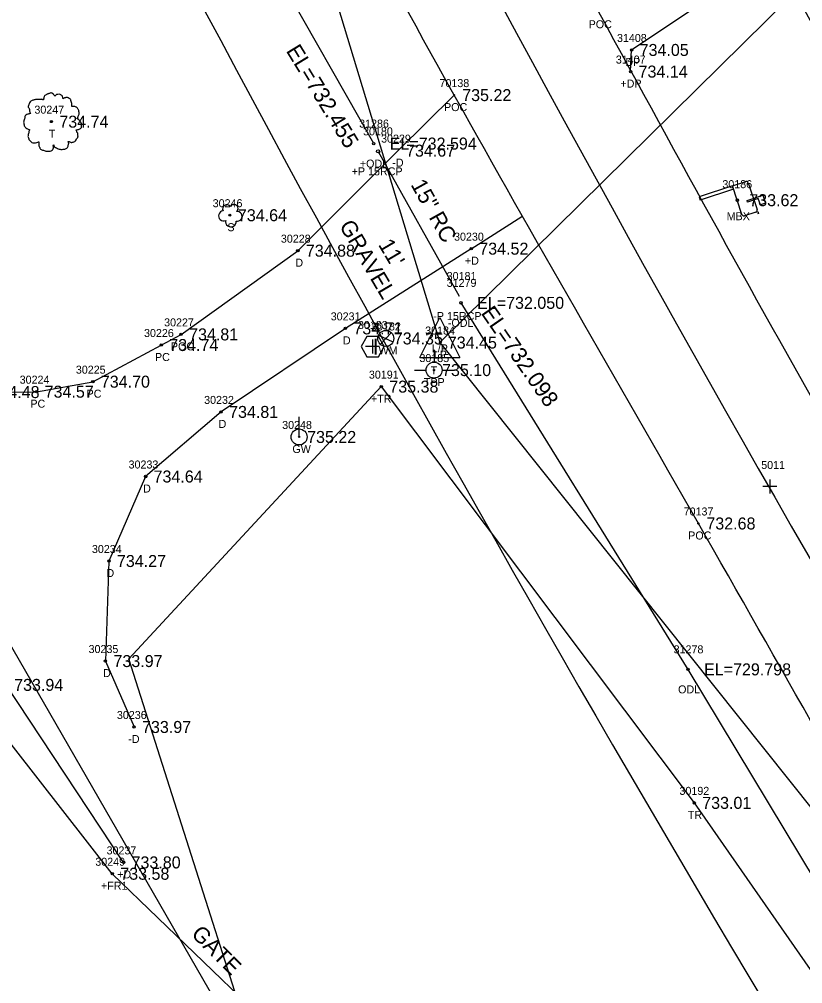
# Model space of a CAD drawing. Extents: x 1375131 to 1378678, y 999028 to 1004053.
# Drawn here: x 1376880.1 to 1376977.9, y 1002249 to 1002369.5 of the extents above; entities that cross this region are included whole.
import ezdxf

# ---------------------------------------------------------------- set-up
doc = ezdxf.new("R2010")
doc.units = 0
for name, color, linetype in [('Default', 7, 'Continuous'), ('RD_EX_BldgApp', 7, 'Continuous'), ('RD_EX_BldgApp_txCode', 7, 'Continuous'), ('RD_EX_DR_Pipe', 7, 'Continuous'), ('RD_EX_DR_Pipe_txCode', 7, 'Continuous'), ('RD_EX_Driveway', 7, 'Continuous'), ('RD_EX_Driveway_txCode', 7, 'Continuous'), ('RD_EX_DV_Prop', 7, 'Continuous'), ('RD_EX_Fence_Other', 7, 'Continuous'), ('RD_EX_Fence_Other_txCode', 7, 'Continuous'), ('RD_EX_H2O', 7, 'Continuous'), ('RD_EX_H2O_txCode', 7, 'Continuous'), ('RD_EX_Road', 7, 'Continuous'), ('RD_EX_Road_txCode', 7, 'Continuous'), ('RD_EX_RW', 7, 'Continuous'), ('RD_EX_SU_Elec', 7, 'Continuous'), ('RD_EX_SU_TX_Nonpot', 7, 'Continuous'), ('RD_EX_TX_BldgApp_ELEV', 7, 'Continuous'), ('RD_EX_TX_Driveway_ELEV', 7, 'Continuous'), ('RD_EX_TX_Fence_Other_ELEV', 7, 'Continuous'), ('RD_EX_TX_H2O_ELEV', 7, 'Continuous'), ('RD_EX_TX_Road_ELEV', 7, 'Continuous'), ('RD_EX_TX_UT_ELEV', 7, 'Continuous'), ('RD_EX_TX_VEG_ELEV', 7, 'Continuous'), ('RD_EX_UT', 7, 'Continuous'), ('RD_EX_UT_txCode', 7, 'Continuous'), ('RD_EX_VEG', 7, 'Continuous'), ('RD_EX_VEG_txCode', 7, 'Continuous'), ('RD_HC_Cl', 7, 'Continuous'), ('RD_SMD_Locator', 7, 'Continuous'), ('RD_TX_Drainage', 7, 'Continuous'), ('RD_TX_Misc2', 7, 'Continuous'), ('RD_TX_Pipe_ElevEX', 7, 'Continuous')]:
    doc.layers.add(name, color=color, linetype=linetype)

msp = doc.modelspace()

# ---------------------------------------------------------------- linework, layer by layer
at = {"layer": 'Default'}
for p, q in [((1376924.21, 1002329.43), (1376924.21, 1002327.68)), ((1376925.08, 1002328.56), (1376923.33, 1002328.56)), ((1376973.86, 1002311.95), (1376973.86, 1002310.2)), ((1376974.73, 1002311.07), (1376972.98, 1002311.07))]:
    msp.add_line(p, q, dxfattribs=at)
at = {"layer": 'RD_EX_BldgApp'}
for p, q in [((1376969.17, 1002348.65), (1376970.83, 1002349.2)), ((1376969.17, 1002348.65), (1376964.99, 1002347.27)), ((1376969.31, 1002348.25), (1376965.12, 1002346.87)), ((1376970.36, 1002345.06), (1376969.17, 1002348.65)), ((1376971.15, 1002349.04), (1376972.26, 1002345.69)), ((1376964.99, 1002347.27), (1376965.12, 1002346.87)), ((1376970.99, 1002346.81), (1376972.98, 1002347.47)), ((1376971.05, 1002346.63), (1376970.99, 1002346.81)), ((1376972.4, 1002347.07), (1376971.05, 1002346.63)), ((1376972.66, 1002346.28), (1376972.4, 1002347.07)), ((1376972.98, 1002347.47), (1376973.3, 1002346.49)), ((1376973.3, 1002346.49), (1376972.66, 1002346.28)), ((1376972.1, 1002345.37), (1376970.68, 1002344.9)), ((1376972.1, 1002345.37), (1376972.34, 1002345.45)), ((1376972.42, 1002345.21), (1376972.3, 1002345.17)), ((1376972.34, 1002345.45), (1376972.42, 1002345.21))]:
    msp.add_line(p, q, dxfattribs=at)
for centre, start, end in [((1376970.91, 1002348.96), 18.3234, 108.3234), ((1376972.02, 1002345.61), 288.3234, 18.3234), ((1376970.6, 1002345.14), 198.3234, 288.3234)]:
    msp.add_arc(centre, 0.25, start, end, dxfattribs=at)
at = {"layer": 'RD_EX_DR_Pipe'}
msp.add_line((1376924.89, 1002352.96), (1376935.01, 1002334.88), dxfattribs=at)
at = {"layer": 'RD_EX_Driveway'}
msp.add_line((1376936.53, 1002340.8), (1376942.86, 1002344.81), dxfattribs=at)
for points in [[(1376911, 1002403.28), (1376904.12, 1002405.28), (1376902.61, 1002405.41), (1376898.14, 1002404.97), (1376891.9, 1002404.07), (1376878.32, 1002397.35), (1376865.82, 1002389.76), (1376856.77, 1002381.29), (1376852.77, 1002374.27), (1376851.72, 1002365.55), (1376852.45, 1002354.79), (1376854.03, 1002345.76), (1376868.77, 1002323.94), (1376875.45, 1002322.88), (1376882.22, 1002322.93), (1376889.24, 1002324.18), (1376897.79, 1002328.76), (1376900.27, 1002330.09), (1376914.86, 1002340.55), (1376927.38, 1002353.05), (1376934.4, 1002359.99)], [(1376956.44, 1002362.93), (1376956.57, 1002365.63), (1376967.2, 1002372.83), (1376960.83, 1002383.95), (1376951.12, 1002382.71), (1376946.21, 1002383.24)], [(1376893.08, 1002264.11), (1376878.41, 1002286.29), (1376842.77, 1002332.19), (1376829.79, 1002366.92)], [(1376936.53, 1002340.8), (1376920.8, 1002330.84), (1376905.27, 1002320.4), (1376895.83, 1002312.33), (1376891.25, 1002301.77), (1376890.82, 1002289.27), (1376894.39, 1002281.03)]]:
    msp.add_lwpolyline(points, dxfattribs=at)
at = {"layer": 'RD_EX_DV_Prop'}
msp.add_lwpolyline([(1376724.42, 1002117.06), (1376637.57, 1002230.63), (1376389.38, 1002558.79), (1376664.3, 1002769.81), (1376707.09, 1002654.77), (1376824.56, 1002385.67), (1376921.89, 1002216.69), (1376947.76, 1002098.6)], dxfattribs=at)
at = {"layer": 'RD_EX_Fence_Other'}
msp.add_line((1376891.67, 1002262.69), (1376914.2, 1002240.98), dxfattribs=at)
msp.add_lwpolyline([(1376891.67, 1002262.69), (1376866.96, 1002294.33), (1376854.05, 1002303.56)], dxfattribs=at)
at = {"layer": 'RD_EX_H2O'}
for points in [[(1376924.34, 1002353.93), (1376912.06, 1002375.56), (1376899.82, 1002397.17)], [(1377136.38, 1001999.34), (1377116.95, 1002033.41), (1377090.35, 1002075.98), (1377065.42, 1002117.59), (1377038.3, 1002163.03), (1377017.87, 1002196.37), (1376989.72, 1002244.93), (1376963.62, 1002288.23), (1376935.26, 1002334.03)]]:
    msp.add_lwpolyline(points, dxfattribs=at)
at = {"layer": 'RD_EX_Road'}
for points in [[(1377013.31, 1002264.91), (1376982.81, 1002315.68), (1376952.47, 1002370.34), (1376923.17, 1002424.32), (1376895.64, 1002480.03), (1376870.11, 1002535.05), (1376846.33, 1002588.86), (1376822.29, 1002645.03), (1376786.56, 1002736.46)], [(1376994.75, 1002253.91), (1376964.91, 1002306.46), (1376934.4, 1002359.99), (1376904.77, 1002415.49), (1376877.27, 1002471.51), (1376851.04, 1002526.89), (1376827.48, 1002581.62), (1376804.19, 1002637.82), (1376768.46, 1002728.84)]]:
    msp.add_spline(points, degree=3, dxfattribs=at)
at = {"layer": 'RD_EX_RW'}
for radius in [2767, 2833]:
    msp.add_arc((1379404.86, 1003700.11), radius, 200.26995, 211.13117, dxfattribs=at)
at = {"layer": 'RD_EX_SU_Elec'}
for p, q in [((1376829.24, 1002670.59), (1376932.6, 1002329.07)), ((1376932.6, 1002329.07), (1377119.53, 1002513.39))]:
    msp.add_line(p, q, dxfattribs=at)
msp.add_lwpolyline([(1376932.6, 1002329.07), (1377163.28, 1002039.96), (1377247.04, 1001903.65)], dxfattribs=at)
at = {"layer": 'RD_EX_SU_TX_Nonpot'}
msp.add_lwpolyline([(1376925.65, 1002328.56), (1376924.93, 1002329.81), (1376923.49, 1002329.81), (1376922.76, 1002328.56), (1376923.49, 1002327.3), (1376924.93, 1002327.3)], close=True, dxfattribs=at)
at = {"layer": 'RD_EX_UT'}
for p, q in [((1376930.1, 1002327.2), (1376932.6, 1002332.2)), ((1376932.6, 1002332.2), (1376935.1, 1002327.2)), ((1376924.94, 1002330), (1376926.75, 1002329.15)), ((1376925.18, 1002328.85), (1376926.51, 1002330.3)), ((1376931.88, 1002328.16), (1376931.88, 1002326.63)), ((1376930.1, 1002327.2), (1376935.1, 1002327.2)), ((1376929.42, 1002325.63), (1376930.88, 1002325.63)), ((1376932.88, 1002325.63), (1376934.42, 1002325.63)), ((1376915.02, 1002317.27), (1376915.02, 1002319.77))]:
    msp.add_line(p, q, dxfattribs=at)
for centre in [(1376925.85, 1002329.58), (1376931.88, 1002325.63), (1376915.02, 1002317.27)]:
    msp.add_circle(centre, 1, dxfattribs=at)
at = {"layer": 'RD_EX_VEG'}
for points in [[(1377227.27, 1001786.89), (1377002.39, 1002037.45), (1376937.65, 1002151.76), (1376893.73, 1002289.53), (1376925.29, 1002323.56)], [(1376925.29, 1002323.56), (1376964.39, 1002271.55), (1376999.6, 1002220.98), (1377033.75, 1002161.52), (1377072.45, 1002098.21), (1377110.65, 1002037.08), (1377148.79, 1001977.33), (1377186.7, 1001917.17), (1377238.51, 1001843.58), (1377265.98, 1001789.91), (1377290.89, 1001746.87), (1377322.19, 1001689.75), (1377357.87, 1001632.38)]]:
    msp.add_lwpolyline(points, dxfattribs=at)
for centre, radius in [((1376884.06, 1002356.67), 0.125), ((1376884.06, 1002356.66), 0.00005), ((1376906.37, 1002344.98), 0.125)]:
    msp.add_circle(centre, radius, dxfattribs=at)
for centre, radius, start, end in [((1376905.58, 1002344.9), 0.628, 96.4518, 294.734), ((1376906, 1002345.75), 0.542, 34.9763, 204.756), ((1376906.89, 1002345.83), 0.497, 308.7626, 152.0467), ((1376906.49, 1002344.18), 0.659, 166.8827, 5.7589), ((1376907.28, 1002344.84), 0.609, 256.5667, 98.1046)]:
    msp.add_arc(centre, radius, start, end, dxfattribs=at)
for points in [[(1376884.13, 1002360.25), (1376883.98, 1002360.26), (1376883.82, 1002360.21), (1376883.69, 1002360.16), (1376883.58, 1002360.12), (1376883.47, 1002360.07), (1376883.32, 1002359.99), (1376883.2, 1002359.89), (1376883.14, 1002359.76), (1376883.12, 1002359.65), (1376883.09, 1002359.51), (1376883.09, 1002359.42), (1376883.03, 1002359.41), (1376882.95, 1002359.42), (1376882.83, 1002359.46), (1376882.7, 1002359.46), (1376882.58, 1002359.46), (1376882.4, 1002359.45), (1376882.23, 1002359.45), (1376882.09, 1002359.42), (1376881.93, 1002359.4), (1376881.74, 1002359.34), (1376881.57, 1002359.28), (1376881.42, 1002359.15), (1376881.29, 1002358.91), (1376881.23, 1002358.74), (1376881.15, 1002358.61), (1376881.23, 1002358.39), (1376881.32, 1002358.21), (1376881.33, 1002358.11), (1376881.37, 1002357.9), (1376881.42, 1002357.79), (1376881.48, 1002357.69), (1376881.44, 1002357.68), (1376881.25, 1002357.65), (1376881.1, 1002357.6), (1376880.89, 1002357.49), (1376880.78, 1002357.38), (1376880.73, 1002357.21), (1376880.72, 1002357.04), (1376880.67, 1002356.94), (1376880.63, 1002356.8), (1376880.62, 1002356.76), (1376880.59, 1002356.6), (1376880.64, 1002356.38), (1376880.65, 1002356.2), (1376880.72, 1002356.09), (1376880.79, 1002356), (1376880.88, 1002355.88), (1376881.08, 1002355.76), (1376881.24, 1002355.71), (1376881.34, 1002355.7), (1376881.25, 1002355.45), (1376881.23, 1002355.28), (1376881.17, 1002355.08), (1376881.17, 1002355.04), (1376881.14, 1002354.8), (1376881.22, 1002354.64), (1376881.25, 1002354.45), (1376881.34, 1002354.34), (1376881.48, 1002354.19), (1376881.64, 1002354.08), (1376881.89, 1002354.01), (1376882.09, 1002354.03), (1376882.38, 1002354.11), (1376882.5, 1002354.15), (1376882.49, 1002354.06), (1376882.5, 1002353.88), (1376882.5, 1002353.67), (1376882.58, 1002353.5), (1376882.63, 1002353.37), (1376882.7, 1002353.24), (1376882.87, 1002353.13), (1376883.07, 1002353.09), (1376883.28, 1002353.02), (1376883.5, 1002352.98), (1376883.75, 1002352.97), (1376884.05, 1002353.04), (1376884.19, 1002353.1), (1376884.24, 1002353.19), (1376884.34, 1002353.38), (1376884.32, 1002353.49), (1376884.33, 1002353.79), (1376884.38, 1002353.7), (1376884.47, 1002353.53), (1376884.72, 1002353.38), (1376884.92, 1002353.29), (1376885.15, 1002353.22), (1376885.3, 1002353.18), (1376885.54, 1002353.22), (1376885.73, 1002353.25), (1376885.91, 1002353.32), (1376886.06, 1002353.45), (1376886.15, 1002353.59), (1376886.18, 1002353.73), (1376886.21, 1002353.91), (1376886.24, 1002354)], [(1376886.24, 1002354), (1376886.2, 1002354.09), (1376886.18, 1002354.21), (1376886.21, 1002354.2), (1376886.3, 1002354.18), (1376886.44, 1002354.11), (1376886.55, 1002354.08), (1376886.71, 1002354.09), (1376886.85, 1002354.14), (1376887.08, 1002354.28), (1376887.21, 1002354.51), (1376887.35, 1002354.71), (1376887.39, 1002354.88), (1376887.36, 1002354.99), (1376887.35, 1002355.24), (1376887.25, 1002355.36), (1376887.23, 1002355.43), (1376887.18, 1002355.63), (1376887.21, 1002355.65), (1376887.35, 1002355.68), (1376887.54, 1002355.74), (1376887.68, 1002355.8), (1376887.79, 1002355.89), (1376887.83, 1002356), (1376887.81, 1002356.2), (1376887.84, 1002356.4), (1376887.8, 1002356.48), (1376887.75, 1002356.55), (1376887.71, 1002356.65), (1376887.64, 1002356.73), (1376887.59, 1002356.8), (1376887.54, 1002356.85), (1376887.48, 1002356.93), (1376887.39, 1002356.99), (1376887.31, 1002357.01), (1376887.29, 1002357.09), (1376887.36, 1002357.19), (1376887.39, 1002357.24), (1376887.4, 1002357.35), (1376887.51, 1002357.53), (1376887.54, 1002357.73), (1376887.51, 1002357.94), (1376887.49, 1002358.08), (1376887.41, 1002358.21), (1376887.31, 1002358.34), (1376887.25, 1002358.43), (1376887.16, 1002358.49), (1376887, 1002358.55), (1376886.88, 1002358.58), (1376886.7, 1002358.58), (1376886.6, 1002358.6), (1376886.61, 1002358.63), (1376886.61, 1002358.7), (1376886.61, 1002358.84), (1376886.58, 1002359.06), (1376886.5, 1002359.31), (1376886.5, 1002359.33), (1376886.45, 1002359.45), (1376886.34, 1002359.55), (1376886.25, 1002359.6), (1376886.15, 1002359.66), (1376886.03, 1002359.67), (1376885.88, 1002359.67), (1376885.74, 1002359.65), (1376885.64, 1002359.6), (1376885.55, 1002359.54), (1376885.51, 1002359.61), (1376885.46, 1002359.76), (1376885.44, 1002359.84), (1376885.36, 1002359.92), (1376885.25, 1002360.02), (1376885.03, 1002360.09), (1376884.72, 1002360.05), (1376884.57, 1002359.95), (1376884.49, 1002359.86), (1376884.47, 1002359.92), (1376884.37, 1002360.02), (1376884.32, 1002360.11), (1376884.23, 1002360.17), (1376884.15, 1002360.22), (1376884.1, 1002360.25)]]:
    msp.add_spline(points, degree=3, dxfattribs=at)
at = {"layer": 'RD_HC_Cl'}
msp.add_arc((1379404.86, 1003700.11), 2800, 200.26995, 211.13117, dxfattribs=at)
at = {"layer": 'RD_SMD_Locator'}
for centre, radius in [((1376956.57, 1002365.63), 0.15), ((1376956.44, 1002362.93), 0.15), ((1376934.4, 1002359.99), 0.075), ((1376884.06, 1002356.67), 0.075), ((1376924.34, 1002353.93), 0.15), ((1376924.89, 1002352.96), 0.2), ((1376969.77, 1002346.86), 0.15), ((1376906.37, 1002344.98), 0.075), ((1376936.53, 1002340.8), 0.15), ((1376914.86, 1002340.55), 0.15), ((1376935.26, 1002334.03), 0.15), ((1376900.27, 1002330.09), 0.15), ((1376920.8, 1002330.84), 0.15), ((1376897.79, 1002328.76), 0.15), ((1376925.85, 1002329.58), 0.075), ((1376932.6, 1002329.07), 0.075), ((1376931.88, 1002325.63), 0.075), ((1376889.24, 1002324.18), 0.15), ((1376882.22, 1002322.93), 0.15), ((1376925.29, 1002323.56), 0.15), ((1376905.27, 1002320.4), 0.15), ((1376915.02, 1002317.27), 0.075), ((1376895.83, 1002312.33), 0.15), ((1376964.91, 1002306.46), 0.075), ((1376891.25, 1002301.77), 0.15), ((1376890.82, 1002289.27), 0.15), ((1376963.62, 1002288.23), 0.15), ((1376894.39, 1002281.03), 0.15), ((1376964.39, 1002271.55), 0.15), ((1376893.08, 1002264.11), 0.15), ((1376891.67, 1002262.69), 0.15)]:
    msp.add_circle(centre, radius, dxfattribs=at)

# ---------------------------------------------------------------- texts
at = {"layer": 'Default'}
for s, p in [('30183', (1376922.37, 1002330.76)), ('5011', (1376972.76, 1002313.27))]:
    msp.add_text(s, height=1, dxfattribs=at).set_placement(p)
at = {"layer": 'RD_EX_BldgApp_txCode'}
for s, p in [('30186', (1376967.91, 1002348.36)), ('MBX', (1376968.45, 1002344.36))]:
    msp.add_text(s, height=1, dxfattribs=at).set_placement(p)
at = {"layer": 'RD_EX_DR_Pipe_txCode'}
for s, p in [('30180', (1376923.01, 1002354.96)), ('+P 15RCP', (1376921.59, 1002349.96)), ('30181', (1376933.46, 1002336.88)), ('-P 15RCP', (1376931.79, 1002331.88))]:
    msp.add_text(s, height=1, dxfattribs=at).set_placement(p)
at = {"layer": 'RD_EX_Driveway_txCode'}
for s, p in [('31408', (1376954.74, 1002366.63)), ('31407', (1376954.6, 1002363.93)), ('DP', (1376955.79, 1002363.63)), ('+DP', (1376955.17, 1002360.93)), ('30229', (1376925.26, 1002354.05)), ('-D', (1376926.66, 1002351.05)), ('30228', (1376912.74, 1002341.55)), ('30230', (1376934.38, 1002341.8)), ('D', (1376914.55, 1002338.55)), ('+D', (1376935.74, 1002338.8)), ('30231', (1376918.97, 1002331.84)), ('30227', (1376898.15, 1002331.09)), ('30226', (1376895.64, 1002329.76)), ('POC', (1376899, 1002328.09)), ('D', (1376920.49, 1002328.84)), ('PC', (1376897.01, 1002326.76)), ('30225', (1376887.12, 1002325.18)), ('30224', (1376880.1, 1002323.93)), ('PC', (1376888.46, 1002322.18)), ('PC', (1376881.44, 1002320.93)), ('30232', (1376903.15, 1002321.4)), ('D', (1376904.96, 1002318.4)), ('30233', (1376893.71, 1002313.33)), ('D', (1376895.52, 1002310.33)), ('30234', (1376889.13, 1002302.77)), ('D', (1376890.94, 1002299.77)), ('30235', (1376888.71, 1002290.27)), ('D', (1376890.52, 1002287.27)), ('30236', (1376892.25, 1002282.03)), ('-D', (1376893.67, 1002279.03)), ('30237', (1376890.96, 1002265.11)), ('+D', (1376892.28, 1002262.11))]:
    msp.add_text(s, height=1, dxfattribs=at).set_placement(p)
at = {"layer": 'RD_EX_Fence_Other_txCode'}
for s, p in [('30249', (1376889.55, 1002263.69)), ('+FR1', (1376890.26, 1002260.69))]:
    msp.add_text(s, height=1, dxfattribs=at).set_placement(p)
at = {"layer": 'RD_EX_H2O_txCode'}
for s, p in [('31286', (1376922.52, 1002355.93)), ('+ODL', (1376922.61, 1002350.93)), ('31279', (1376933.46, 1002336.03)), ('-ODL', (1376933.61, 1002331.03)), ('31278', (1376961.82, 1002290.23)), ('ODL', (1376962.38, 1002285.23))]:
    msp.add_text(s, height=1, dxfattribs=at).set_placement(p)
at = {"layer": 'RD_EX_Road_txCode'}
for s, p in [('POC', (1376951.2, 1002368.34)), ('70138', (1376932.56, 1002360.99)), ('POC', (1376933.13, 1002357.99)), ('70137', (1376963.07, 1002307.46)), ('POC', (1376963.64, 1002304.46))]:
    msp.add_text(s, height=1, dxfattribs=at).set_placement(p)
at = {"layer": 'RD_EX_SU_TX_Nonpot'}
msp.add_text('I', height=2, dxfattribs=at).set_placement((1376924.21, 1002327.56))
at = {"layer": 'RD_EX_TX_BldgApp_ELEV'}
msp.add_text('733.62', height=1.5, dxfattribs=at).set_placement((1376971.27, 1002346.11))
at = {"layer": 'RD_EX_TX_Driveway_ELEV'}
for s, p in [('734.05', (1376957.57, 1002364.88)), ('734.14', (1376957.44, 1002362.18)), ('734.67', (1376928.38, 1002352.3)), ('734.88', (1376915.86, 1002339.8)), ('734.52', (1376937.53, 1002340.05)), ('734.71', (1376921.8, 1002330.09)), ('734.81', (1376901.27, 1002329.34)), ('734.74', (1376898.79, 1002328.01)), ('734.70', (1376890.24, 1002323.43)), ('734.48', (1376876.45, 1002322.13)), ('734.57', (1376883.22, 1002322.18)), ('734.81', (1376906.27, 1002319.65)), ('734.64', (1376896.83, 1002311.58)), ('734.27', (1376892.25, 1002301.02)), ('733.97', (1376891.82, 1002288.52)), ('733.94', (1376879.41, 1002285.54)), ('733.97', (1376895.39, 1002280.28)), ('733.80', (1376894.08, 1002263.36))]:
    msp.add_text(s, height=1.5, dxfattribs=at).set_placement(p)
at = {"layer": 'RD_EX_TX_Fence_Other_ELEV'}
msp.add_text('733.58', height=1.5, dxfattribs=at).set_placement((1376892.67, 1002261.94))
at = {"layer": 'RD_EX_TX_H2O_ELEV'}
for s, p in [('EL=732.594', (1376926.34, 1002353.18)), ('EL=732.050', (1376937.26, 1002333.28)), ('EL=729.798', (1376965.62, 1002287.48))]:
    msp.add_text(s, height=1.5, dxfattribs=at).set_placement(p)
at = {"layer": 'RD_EX_TX_Road_ELEV'}
for s, p in [('735.22', (1376935.4, 1002359.24)), ('732.68', (1376965.91, 1002305.71))]:
    msp.add_text(s, height=1.5, dxfattribs=at).set_placement(p)
at = {"layer": 'RD_EX_TX_UT_ELEV'}
for s, p in [('734.35', (1376926.85, 1002328.83)), ('734.45', (1376933.6, 1002328.32)), ('735.10', (1376932.88, 1002324.88)), ('735.22', (1376916.02, 1002316.52))]:
    msp.add_text(s, height=1.5, dxfattribs=at).set_placement(p)
at = {"layer": 'RD_EX_TX_VEG_ELEV'}
for s, p in [('734.74', (1376885.06, 1002355.92)), ('734.64', (1376907.37, 1002344.23)), ('735.38', (1376926.29, 1002322.81)), ('733.01', (1376965.39, 1002270.8))]:
    msp.add_text(s, height=1.5, dxfattribs=at).set_placement(p)
at = {"layer": 'RD_EX_UT'}
for s, p in [('L/P', (1376931.6, 1002327.84)), ('T', (1376931.46, 1002325.1))]:
    msp.add_text(s, height=1, dxfattribs=at).set_placement(p)
at = {"layer": 'RD_EX_UT_txCode'}
for s, p in [('30182', (1376924.02, 1002330.58)), ('30184', (1376930.77, 1002330.07)), ('WM', (1376924.95, 1002327.58)), ('30185', (1376930.05, 1002326.63)), ('LP', (1376931.84, 1002327.07)), ('TPP', (1376930.61, 1002323.63)), ('30248', (1376912.9, 1002318.27)), ('GW', (1376914.18, 1002315.27))]:
    msp.add_text(s, height=1, dxfattribs=at).set_placement(p)
at = {"layer": 'RD_EX_VEG_txCode'}
for s, p in [('30247', (1376881.94, 1002357.67)), ('T', (1376883.74, 1002354.67)), ('30246', (1376904.22, 1002345.98)), ('S', (1376906.06, 1002342.98)), ('30191', (1376923.74, 1002324.56)), ('+TR', (1376924, 1002321.56)), ('30192', (1376962.55, 1002272.55)), ('TR', (1376963.59, 1002269.55))]:
    msp.add_text(s, height=1, dxfattribs=at).set_placement(p)
at = {"layer": 'RD_TX_Drainage'}
msp.add_text('15" RC', height=2, rotation=299.0057, dxfattribs=at).set_placement((1376928.92, 1002348.81))
at = {"layer": 'RD_TX_Misc2'}
for s, rotation, p in [('GRAVEL', 300.4862, (1376919.98, 1002343.66)), ("11'", 300.4862, (1376924.85, 1002341.31)), ('GATE', 314.8518, (1376901.43, 1002255.04))]:
    msp.add_text(s, height=2, rotation=rotation, dxfattribs=at).set_placement(p)
at = {"layer": 'RD_TX_Pipe_ElevEX'}
for s, rotation, p in [('EL=732.455', 301.369, (1376913.33, 1002365.53)), ('EL=732.098', 304.6991, (1376937.67, 1002332.75))]:
    msp.add_text(s, height=2, rotation=rotation, dxfattribs=at).set_placement(p)

doc.saveas('drawing.dxf')
